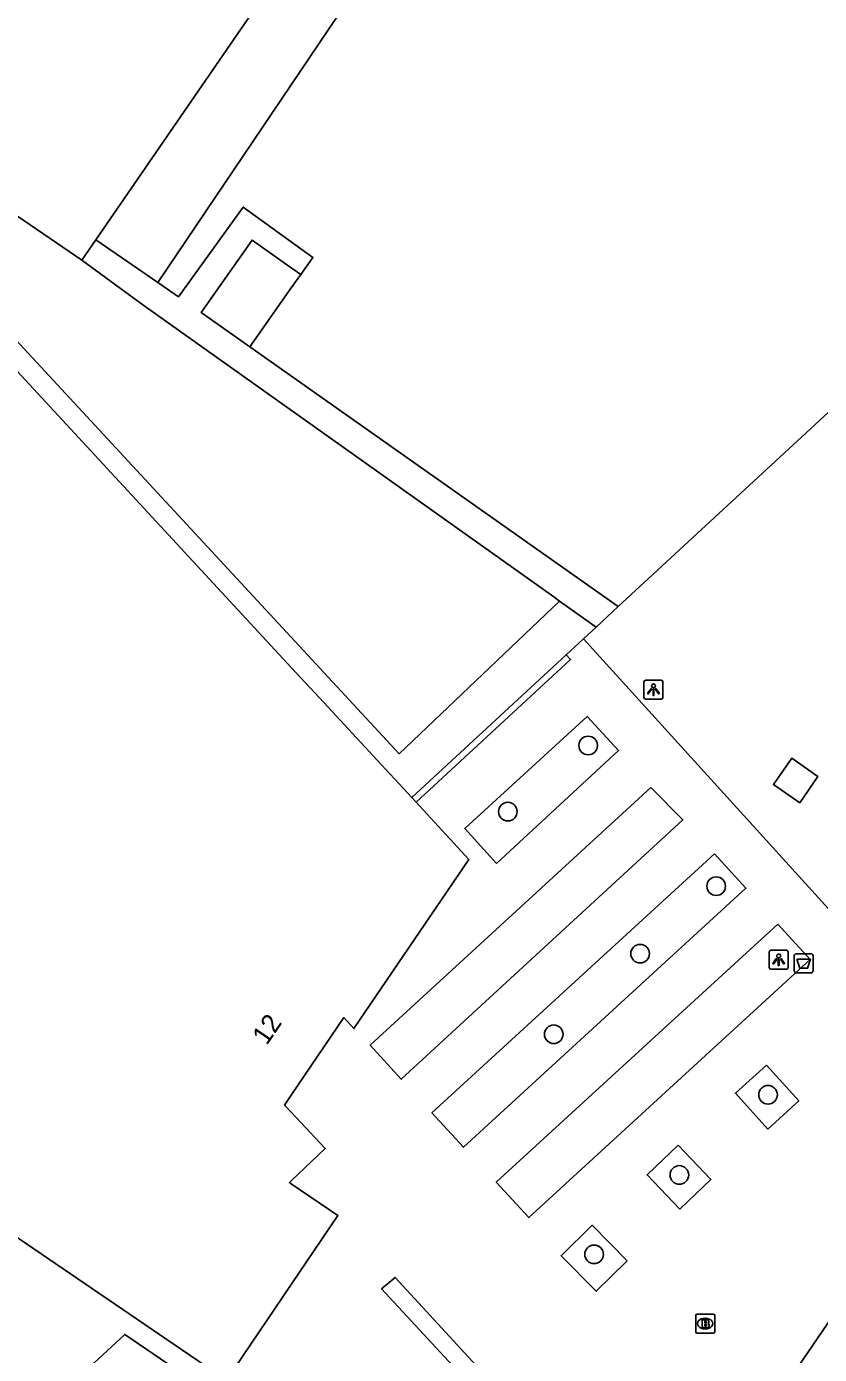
# Model space of a CAD drawing. Extents: x 157154 to 159278, y 385000 to 386650.
# Drawn here: x 158486.1 to 158527.7, y 385465.5 to 385535.3 of the extents above; entities that cross this region are included whole.
import ezdxf

# ---------------------------------------------------------------- set-up
doc = ezdxf.new("R2010")
doc.units = 0
for name, color, linetype in [('IMGEO_Afvalbak', 7, 'Continuous'), ('IMGEO_Boom', 7, 'Continuous'), ('IMGEO_Brandkraan', 7, 'Continuous'), ('IMGEO_Gemengd_bos', 7, 'Continuous'), ('IMGEO_Groenvoorziening', 7, 'Continuous'), ('IMGEO_Hek', 7, 'Continuous'), ('IMGEO_Lichtpunt', 7, 'Continuous'), ('IMGEO_Muur', 7, 'Continuous'), ('IMGEO_Pand', 7, 'Continuous'), ('IMGEO_Pand_nummerreeks', 7, 'Continuous'), ('IMGEO_Voetpad_open', 7, 'Continuous')]:
    doc.layers.add(name, color=color, linetype=linetype)

msp = doc.modelspace()

# ---------------------------------------------------------------- linework, layer by layer
at = {"layer": 'IMGEO_Afvalbak'}
for p, q in [((158526.519, 385486.568), (158527.309, 385486.568)), ((158527.309, 385486.568), (158526.519, 385486.568)), ((158526.419, 385485.668), (158526.419, 385486.468)), ((158526.419, 385486.468), (158526.419, 385485.668)), ((158527.409, 385486.468), (158527.409, 385485.668)), ((158527.409, 385485.668), (158527.409, 385486.468)), ((158527.309, 385485.568), (158526.519, 385485.568)), ((158526.519, 385485.568), (158527.309, 385485.568))]:
    msp.add_line(p, q, dxfattribs=at)
msp.add_lwpolyline([(158526.562, 385486.282), (158527.266, 385486.282), (158527.117, 385485.812), (158526.711, 385485.812), (158526.562, 385486.282)], dxfattribs=at)
for centre, start, end in [((158526.519, 385486.468), 90, 180), ((158526.519, 385486.468), 90, 180), ((158527.309, 385486.468), 0, 90), ((158527.309, 385486.468), 360, 90), ((158526.519, 385485.668), 180, 270), ((158526.519, 385485.668), 180, 270), ((158527.309, 385485.668), 270, 0), ((158527.309, 385485.668), 270, 0)]:
    msp.add_arc(centre, 0.1, start, end, dxfattribs=at)
at = {"layer": 'IMGEO_Boom'}
for centre in [(158515.593, 385497.506), (158511.376, 385494.032), (158522.32, 385490.12), (158518.322, 385486.575), (158513.786, 385482.342), (158525.042, 385479.165), (158520.385, 385474.954), (158515.905, 385470.785)]:
    msp.add_circle(centre, 0.489, dxfattribs=at)
at = {"layer": 'IMGEO_Brandkraan'}
for p, q in [((158521.241, 385466.721), (158521.241, 385467.573)), ((158521.316, 385467.647), (158522.168, 385467.647)), ((158521.729, 385467.427), (158521.754, 385467.427)), ((158522.242, 385467.573), (158522.242, 385466.721)), ((158522.168, 385466.647), (158521.316, 385466.647)), ((158521.752, 385466.867), (158521.727, 385466.867))]:
    msp.add_line(p, q, dxfattribs=at)
for points in [[(158521.241, 385466.721), (158521.241, 385467.573)], [(158521.316, 385467.647), (158522.168, 385467.647)], [(158521.589, 385467.347), (158521.589, 385466.947), (158521.802, 385466.947)], [(158521.82, 385467.347), (158521.589, 385467.347)], [(158521.768, 385467.266), (158521.714, 385467.266), (158521.714, 385467.19)], [(158521.714, 385467.19), (158521.767, 385467.19)], [(158521.776, 385467.114), (158521.714, 385467.114), (158521.714, 385467.033)], [(158521.714, 385467.033), (158521.776, 385467.033)], [(158522.242, 385467.573), (158522.242, 385466.721)], [(158522.168, 385466.647), (158521.316, 385466.647)]]:
    msp.add_lwpolyline(points, dxfattribs=at)
for centre, radius, start, end in [((158521.318, 385467.571), 0.0765, 91.55205, 178.44795), ((158521.318, 385467.571), 0.0765, 91.55205, 178.44795), ((158521.769, 385467.228), 0.0379, 267.82845, 90.93552), ((158521.777, 385467.073), 0.0404, 269.87594, 90.50774), ((158521.824, 385467.202), 0.145, 59.4692, 91.53667), ((158521.849, 385467.249), 0.0922, 285.51372, 58.15012), ((158521.854, 385467.057), 0.105, 301.31148, 78.98903), ((158522.166, 385467.571), 0.0765, 1.55205, 88.44795), ((158522.166, 385467.571), 0.0765, 1.55205, 88.44795), ((158521.318, 385466.723), 0.0765, 181.55205, 268.44795), ((158521.318, 385466.723), 0.0765, 181.55205, 268.44795), ((158521.808, 385467.198), 0.251, 268.66757, 293.53466), ((158522.166, 385466.723), 0.0765, 271.55205, 358.44795), ((158522.166, 385466.723), 0.0765, 271.55205, 358.44795)]:
    msp.add_arc(centre, radius, start, end, dxfattribs=at)
for centre, major_axis, ratio, start_param, end_param in [((158521.728, 385467.147), (-0.387, 0.002), 0.722429, 4.712389, 7.853982), ((158521.753, 385467.147), (-0.39, 0.002), 0.717154, 1.570796, 4.712389)]:
    msp.add_ellipse(centre, major_axis=major_axis, ratio=ratio, start_param=start_param, end_param=end_param, dxfattribs=at)
at = {"layer": 'IMGEO_Gemengd_bos'}
for points in [[(158492.995, 385521.811), (158514.468, 385553.679), (158479.187, 385577.434), (158456.911, 385544.351), (158432.421, 385507.98), (158416.718, 385518.918), (158396.828, 385490.709), (158361.673, 385440.849)], [(158561.811, 385531.05), (158548.16, 385533.423), (158517.173, 385504.798)]]:
    msp.add_lwpolyline(points, dxfattribs=at)
at = {"layer": 'IMGEO_Groenvoorziening'}
for points in [[(158489.726, 385524.061), (158499.391, 385538.108)], [(158488.994, 385522.997), (158474.747, 385532.719)]]:
    msp.add_lwpolyline(points, dxfattribs=at)
at = {"layer": 'IMGEO_Hek'}
for points in [[(158548.16, 385533.423), (158517.173, 385504.798), (158516.01, 385503.723)], [(158503.619, 385422.88), (158499.73, 385425.483), (158561.195, 385515.535)], [(158516.01, 385503.723), (158515.341, 385503.105)], [(158515.341, 385503.105), (158514.436, 385502.269)]]:
    msp.add_lwpolyline(points, dxfattribs=at)
at = {"layer": 'IMGEO_Lichtpunt'}
for p, q in [((158518.524, 385500.84), (158518.524, 385500.033)), ((158518.524, 385500.84), (158518.524, 385500.033)), ((158519.426, 385500.935), (158518.618, 385500.935)), ((158519.426, 385500.935), (158518.618, 385500.935)), ((158519.52, 385500.033), (158519.52, 385500.84)), ((158519.52, 385500.033), (158519.52, 385500.84)), ((158518.618, 385499.939), (158519.426, 385499.939)), ((158518.618, 385499.939), (158519.426, 385499.939)), ((158525.104, 385486.655), (158525.104, 385485.848)), ((158525.104, 385486.655), (158525.104, 385485.848)), ((158526.006, 385486.75), (158525.198, 385486.75)), ((158526.006, 385486.75), (158525.198, 385486.75)), ((158526.1, 385485.848), (158526.1, 385486.655)), ((158526.1, 385485.848), (158526.1, 385486.655)), ((158525.198, 385485.754), (158526.006, 385485.754)), ((158525.198, 385485.754), (158526.006, 385485.754))]:
    msp.add_line(p, q, dxfattribs=at)
for points in [[(158518.898, 385500.504), (158518.937, 385500.476), (158518.749, 385500.214), (158518.711, 385500.241), (158518.898, 385500.504)], [(158519.11, 385500.476), (158519.148, 385500.503), (158519.335, 385500.241), (158519.296, 385500.213), (158519.11, 385500.476)], [(158519, 385500.456), (158519.047, 385500.456), (158519.047, 385500.134), (158519, 385500.134), (158519, 385500.456)], [(158525.478, 385486.319), (158525.517, 385486.291), (158525.329, 385486.029), (158525.291, 385486.056), (158525.478, 385486.319)], [(158525.58, 385486.271), (158525.627, 385486.271), (158525.627, 385485.949), (158525.58, 385485.949), (158525.58, 385486.271)], [(158525.69, 385486.291), (158525.728, 385486.318), (158525.915, 385486.056), (158525.876, 385486.028), (158525.69, 385486.291)]]:
    msp.add_lwpolyline(points, dxfattribs=at)
for centre in [(158519.023, 385500.638), (158525.603, 385486.453)]:
    msp.add_circle(centre, 0.0994, dxfattribs=at)
for centre, start, end in [((158518.618, 385500.84), 90, 180), ((158518.618, 385500.84), 90, 180), ((158519.426, 385500.84), 0, 90), ((158519.426, 385500.84), 0, 90), ((158518.618, 385500.033), 180, 270), ((158518.618, 385500.033), 180, 270), ((158519.426, 385500.033), 270, 0), ((158519.426, 385500.033), 270, 360), ((158525.198, 385486.655), 90, 180), ((158525.198, 385486.655), 90, 180), ((158526.006, 385486.655), 0, 90), ((158526.006, 385486.655), 0, 90), ((158525.198, 385485.848), 180, 270), ((158525.198, 385485.848), 180, 270), ((158526.006, 385485.848), 270, 0), ((158526.006, 385485.848), 270, 360)]:
    msp.add_arc(centre, 0.0946, start, end, dxfattribs=at)
at = {"layer": 'IMGEO_Muur'}
for points in [[(158514.436, 385502.269), (158506.322, 385494.771)], [(158514.436, 385502.269), (158514.667, 385502.02), (158514.429, 385501.8)], [(158514.429, 385501.8), (158506.552, 385494.522)], [(158506.552, 385494.522), (158506.322, 385494.771)]]:
    msp.add_lwpolyline(points, dxfattribs=at)
at = {"layer": 'IMGEO_Pand'}
for points in [[(158446.024, 385509.852), (158446.651, 385510.773), (158439.907, 385515.239), (158454.516, 385528.842), (158458.801, 385524.242), (158461.957, 385527.205), (158462.156, 385527.004), (158469.873, 385534.139), (158476.559, 385526.919), (158500, 385501.603), (158501.484, 385500), (158504.733, 385496.491), (158506.322, 385494.771), (158506.552, 385494.522)], [(158497.819, 385518.448), (158495.264, 385520.25), (158497.941, 385524.044), (158500, 385522.591), (158500.495, 385522.242)], [(158497.819, 385518.448), (158500, 385521.54), (158500.495, 385522.242)], [(158526.705, 385494.493), (158525.323, 385495.454), (158526.284, 385496.837), (158527.666, 385495.876), (158526.705, 385494.493)], [(158506.552, 385494.522), (158508.103, 385492.843), (158508.346, 385492.58), (158509.322, 385491.524), (158503.29, 385482.642), (158502.767, 385483.215), (158500, 385479.136), (158499.649, 385478.619), (158500, 385478.244), (158501.784, 385476.338), (158500, 385474.644), (158499.904, 385474.553), (158500, 385474.488), (158502.452, 385472.824), (158500, 385469.198), (158496.602, 385464.173), (158483.325, 385473.205), (158483.227, 385473.272)]]:
    msp.add_lwpolyline(points, dxfattribs=at)
at = {"layer": 'IMGEO_Voetpad_open'}
for points in [[(158474.316, 385532.056), (158473.868, 385531.391), (158477.608, 385527.327), (158505.674, 385497.072), (158514.085, 385505.091)], [(158500.495, 385522.242), (158501.138, 385523.133), (158497.473, 385525.778), (158494.074, 385521.069), (158492.995, 385521.811)], [(158488.994, 385522.997), (158489.726, 385524.061)], [(158492.995, 385521.811), (158489.726, 385524.061)], [(158566.649, 385523.535), (158561.338, 385515.744), (158561.195, 385515.535), (158499.73, 385425.483), (158503.619, 385422.88)], [(158514.085, 385505.091), (158513.782, 385505.306), (158492.207, 385520.642), (158488.994, 385522.997)], [(158517.173, 385504.798), (158497.819, 385518.448)], [(158516.01, 385503.723), (158514.085, 385505.091)], [(158516.01, 385503.723), (158517.173, 385504.798)], [(158515.341, 385503.105), (158516.01, 385503.723)], [(158515.341, 385503.105), (158514.436, 385502.269), (158514.667, 385502.02), (158514.429, 385501.8), (158506.552, 385494.522)], [(158530.932, 385486.248), (158530.775, 385486.104), (158515.341, 385503.105)], [(158510.785, 385491.317), (158509.112, 385493.145), (158515.549, 385499.035), (158517.196, 385497.235), (158510.785, 385491.317)], [(158518.884, 385495.298), (158520.569, 385493.599), (158505.774, 385479.981), (158504.146, 385481.772), (158518.884, 385495.298)], [(158522.225, 385491.811), (158523.878, 385490.008), (158509.043, 385476.407), (158507.39, 385478.21), (158522.225, 385491.811)], [(158525.549, 385488.128), (158527.257, 385486.265), (158512.475, 385472.717), (158510.767, 385474.58), (158525.549, 385488.128)], [(158524.955, 385480.714), (158526.653, 385478.838), (158525.025, 385477.365), (158523.327, 385479.241), (158524.955, 385480.714)], [(158520.314, 385476.516), (158522.038, 385474.722), (158520.415, 385473.163), (158518.691, 385474.957), (158520.314, 385476.516)], [(158517.646, 385470.453), (158516.022, 385468.844), (158514.175, 385470.708), (158515.799, 385472.317), (158517.646, 385470.453)], [(158515.636, 385458.525), (158508.575, 385451.967), (158503.955, 385451.571), (158487.325, 385462.945), (158491.248, 385466.582), (158497.542, 385462.289), (158495.264, 385460.189), (158503.734, 385454.375), (158511.573, 385461.602), (158504.745, 385468.968), (158505.448, 385469.577), (158515.636, 385458.525)]]:
    msp.add_lwpolyline(points, dxfattribs=at)

# ---------------------------------------------------------------- texts
at = {"layer": 'IMGEO_Pand_nummerreeks'}
msp.add_text('12', height=1, rotation=55.8462, dxfattribs=at).set_placement((158498.708, 385481.721))

doc.saveas('drawing.dxf')
